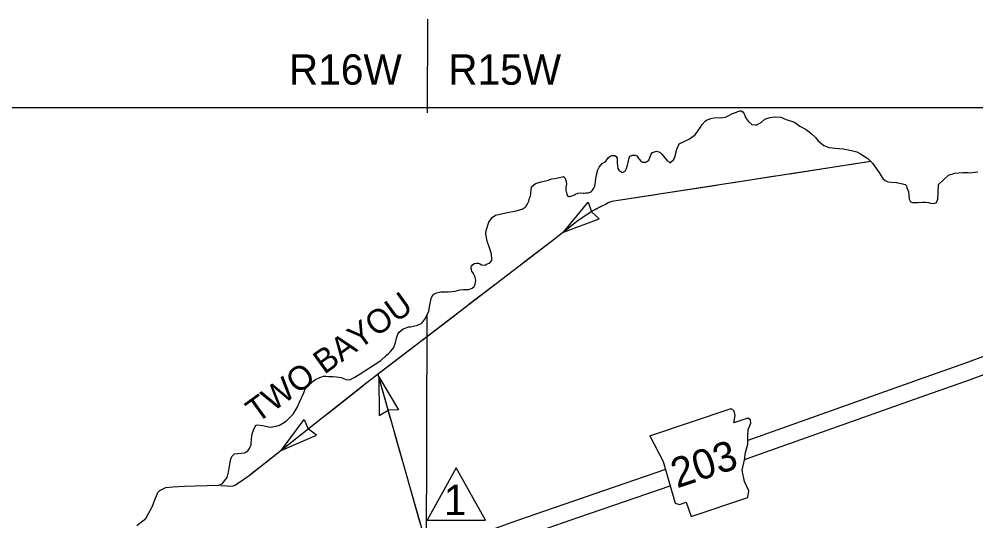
# Model space of a CAD drawing. Extents: x 1373094 to 1376427, y 1168361 to 1170494.
# Drawn here: x 1374665 to 1375232, y 1169290 to 1169586 of the extents above; entities that cross this region are included whole.
import ezdxf

# ---------------------------------------------------------------- set-up
doc = ezdxf.new("R2010")
doc.units = 0
for name, color, linetype in [('Default', 7, 'Continuous'), ('R_Axis', 7, 'Continuous'), ('R_Draft', 7, 'Continuous'), ('R_No Plot', 7, 'Continuous'), ('R_Water Annot', 7, 'Continuous')]:
    doc.layers.add(name, color=color, linetype=linetype)

msp = doc.modelspace()

# ---------------------------------------------------------------- linework, layer by layer
at = {"layer": 'R_Axis'}
for p, q in [((1374987.52, 1169460.32), (1375002.18, 1169478.15)), ((1375002.18, 1169478.15), (1375004.11, 1169472.37)), ((1374987.52, 1169460.32), (1375008.72, 1169468.27)), ((1375008.72, 1169468.27), (1375004.16, 1169472.3)), ((1374878.22, 1169374.82), (1374878.56, 1169351.94)), ((1374878.22, 1169374.82), (1374889.95, 1169355.17)), ((1374878.56, 1169351.94), (1374883.79, 1169355.06)), ((1374889.95, 1169355.17), (1374883.86, 1169355.08)), ((1375088.58, 1169354.46), (1375086.85, 1169355.94)), ((1374820.44, 1169331.13), (1374834.12, 1169349.47)), ((1374834.12, 1169349.47), (1374836.53, 1169343.88)), ((1375088.5, 1169347.6), (1375089.12, 1169351.97)), ((1375096.79, 1169350.37), (1375088.5, 1169347.6)), ((1375089.12, 1169351.97), (1375088.58, 1169354.46)), ((1375098.31, 1169349.39), (1375096.79, 1169350.37)), ((1375098.4, 1169347.34), (1375098.31, 1169349.39)), ((1374841.46, 1169340.17), (1374836.58, 1169343.81)), ((1375096.8, 1169339.67), (1375096.98, 1169343.6)), ((1375096.98, 1169343.6), (1375098.4, 1169347.34)), ((1374820.44, 1169331.13), (1374841.46, 1169340.17)), ((1375038.76, 1169339.85), (1375046.54, 1169324.62)), ((1375096.63, 1169334.86), (1375096.8, 1169339.67)), ((1375095.3, 1169329.95), (1375096.63, 1169334.86)), ((1375094.68, 1169325.58), (1375095.3, 1169329.95)), ((1375046.54, 1169324.62), (1375053.62, 1169299.93)), ((1375093.45, 1169319.52), (1375094.68, 1169325.58)), ((1375094.79, 1169312.83), (1375093.45, 1169319.52)), ((1375097.21, 1169307.39), (1375094.79, 1169312.83)), ((1375096.77, 1169303.38), (1375097.21, 1169307.39)), ((1375053.62, 1169299.93), (1375056.2, 1169299.31)), ((1375056.2, 1169299.31), (1375060.21, 1169300.65)), ((1375060.21, 1169300.65), (1375063.08, 1169292.1)), ((1375063.08, 1169292.1), (1375096.77, 1169303.38))]:
    msp.add_line(p, q, dxfattribs=at)
for points in [[(1374999.19, 1169483.51), (1374999.86, 1169483.38), (1375000.79, 1169483.52), (1375002.25, 1169483.53), (1375003.98, 1169484.21), (1375004.9, 1169485.41), (1375005.56, 1169486.35), (1375006.21, 1169487.56), (1375006.46, 1169489.96), (1375006.71, 1169492.23), (1375007.23, 1169494.24), (1375008.01, 1169497.18), (1375008.8, 1169498.79), (1375010.51, 1169500.93), (1375011.83, 1169501.74), (1375012.76, 1169502.41), (1375013.29, 1169503.22), (1375014.21, 1169504.43), (1375015.13, 1169505.37), (1375016.19, 1169505.77), (1375016.99, 1169505.78), (1375018.06, 1169505.65), (1375018.86, 1169505.12), (1375019.4, 1169504.19), (1375019.4, 1169503.65), (1375019.41, 1169501.39), (1375019.56, 1169499.65), (1375019.84, 1169497.92), (1375020.37, 1169497.12), (1375020.91, 1169496.59), (1375021.71, 1169496.06), (1375021.98, 1169495.93), (1375022.91, 1169495.93), (1375024.1, 1169496.34), (1375024.89, 1169497.95), (1375025.41, 1169499.95), (1375025.79, 1169501.56), (1375026.18, 1169503.29), (1375026.44, 1169504.36), (1375027.1, 1169505.3), (1375028.16, 1169505.98), (1375030.02, 1169505.99), (1375031.09, 1169505.46), (1375031.76, 1169504.39), (1375032.43, 1169503.6), (1375033.5, 1169502.13), (1375034.43, 1169501.74), (1375036.3, 1169501.75), (1375038.02, 1169502.96), (1375038.8, 1169504.57), (1375039.45, 1169506.57), (1375040.38, 1169507.51), (1375041.44, 1169507.92), (1375042.63, 1169508.2), (1375044.1, 1169507.94), (1375044.76, 1169507.54), (1375045.57, 1169506.61), (1375046.77, 1169505.28), (1375048.65, 1169503.16), (1375048.92, 1169502.62), (1375050.25, 1169501.7), (1375050.92, 1169501.43), (1375051.58, 1169502.24), (1375052.64, 1169503.18), (1375053.3, 1169504.12), (1375054.46, 1169508.4), (1375054.72, 1169509.47), (1375056.16, 1169512.55), (1375058.95, 1169513.9), (1375062.13, 1169515.52), (1375065.04, 1169517.54), (1375065.57, 1169517.94), (1375067.28, 1169520.49), (1375068.73, 1169522.37), (1375069.65, 1169523.97), (1375071.36, 1169525.99), (1375072.29, 1169526.66), (1375073.22, 1169527.06), (1375074.81, 1169527.61), (1375076.67, 1169528.02), (1375081.85, 1169528.18), (1375083.44, 1169528.46), (1375084.64, 1169529), (1375087.68, 1169530.49), (1375089.94, 1169531.43), (1375090.73, 1169531.71), (1375091.93, 1169532.11), (1375092.86, 1169532.12), (1375093.79, 1169531.46), (1375094.46, 1169530.39), (1375095.41, 1169528.13), (1375097.02, 1169525.87), (1375099.16, 1169524.01), (1375101.16, 1169523.75), (1375101.95, 1169523.89), (1375104.87, 1169525.51), (1375106.59, 1169526.99), (1375107.78, 1169527.67), (1375109.9, 1169528.21), (1375112.69, 1169528.63), (1375112.96, 1169528.63)], [(1374999.19, 1169483.51), (1374999.86, 1169483.38), (1375000.79, 1169483.52), (1375002.25, 1169483.53), (1375003.98, 1169484.21), (1375004.9, 1169485.41), (1375005.56, 1169486.35), (1375006.21, 1169487.56), (1375006.46, 1169489.96), (1375006.71, 1169492.23), (1375007.23, 1169494.24), (1375008.01, 1169497.18), (1375008.8, 1169498.79), (1375010.51, 1169500.93), (1375011.83, 1169501.74), (1375012.76, 1169502.41), (1375013.29, 1169503.22), (1375014.21, 1169504.43), (1375015.13, 1169505.37), (1375016.19, 1169505.77), (1375016.99, 1169505.78), (1375018.06, 1169505.65), (1375018.86, 1169505.12), (1375019.4, 1169504.19), (1375019.4, 1169503.65), (1375019.41, 1169501.39), (1375019.56, 1169499.65), (1375019.84, 1169497.92), (1375020.37, 1169497.12), (1375020.91, 1169496.59), (1375021.71, 1169496.06), (1375021.98, 1169495.93), (1375022.91, 1169495.93), (1375024.1, 1169496.34), (1375024.89, 1169497.95), (1375025.41, 1169499.95), (1375025.79, 1169501.56), (1375026.18, 1169503.29), (1375026.44, 1169504.36), (1375027.1, 1169505.3), (1375028.16, 1169505.98), (1375030.02, 1169505.99), (1375031.09, 1169505.46), (1375031.76, 1169504.39), (1375032.43, 1169503.6), (1375033.5, 1169502.13), (1375034.43, 1169501.74), (1375036.3, 1169501.75), (1375038.02, 1169502.96), (1375038.8, 1169504.57), (1375039.45, 1169506.57), (1375040.38, 1169507.51), (1375041.44, 1169507.92), (1375042.63, 1169508.2), (1375044.1, 1169507.94), (1375044.76, 1169507.54), (1375045.57, 1169506.61), (1375046.77, 1169505.28), (1375048.65, 1169503.16), (1375048.92, 1169502.62), (1375050.25, 1169501.7), (1375050.92, 1169501.43), (1375051.58, 1169502.24), (1375052.64, 1169503.18), (1375053.3, 1169504.12), (1375054.46, 1169508.4), (1375054.72, 1169509.47), (1375056.16, 1169512.55), (1375058.95, 1169513.9), (1375062.13, 1169515.52), (1375065.04, 1169517.54), (1375065.57, 1169517.94), (1375067.28, 1169520.49), (1375068.73, 1169522.37), (1375069.65, 1169523.97), (1375071.36, 1169525.99), (1375072.29, 1169526.66), (1375073.22, 1169527.06), (1375074.81, 1169527.61), (1375076.67, 1169528.02), (1375081.85, 1169528.18), (1375083.44, 1169528.46), (1375084.64, 1169529), (1375087.68, 1169530.49), (1375089.94, 1169531.43), (1375090.73, 1169531.71), (1375091.93, 1169532.11), (1375092.86, 1169532.12), (1375093.79, 1169531.46), (1375094.46, 1169530.39), (1375095.41, 1169528.13), (1375097.02, 1169525.87), (1375099.16, 1169524.01), (1375101.16, 1169523.75), (1375101.95, 1169523.89), (1375104.87, 1169525.51), (1375106.59, 1169526.99), (1375107.78, 1169527.67), (1375109.9, 1169528.21), (1375112.69, 1169528.63), (1375112.96, 1169528.63)], [(1375112.96, 1169528.63), (1375116.15, 1169528.38), (1375119.48, 1169527.07), (1375124.41, 1169525.36), (1375127.48, 1169523.11), (1375131.22, 1169520.99), (1375134.03, 1169519.01), (1375136.7, 1169516.35), (1375138.44, 1169514.36), (1375141.79, 1169511.71), (1375142.72, 1169511.31), (1375144.85, 1169510.52), (1375148.31, 1169510.14), (1375153.1, 1169509.64), (1375158.16, 1169508.6), (1375161.22, 1169507.81), (1375163.49, 1169506.76), (1375167.76, 1169503.85), (1375170.44, 1169501.19), (1375172.86, 1169497.74), (1375174.6, 1169495.21), (1375176.62, 1169492.02), (1375177.95, 1169490.96), (1375179.55, 1169490.16), (1375181.82, 1169489.91), (1375184.88, 1169489.66), (1375185.28, 1169489.53), (1375187.4, 1169489.14), (1375189.8, 1169488.49), (1375190.6, 1169487.83), (1375190.88, 1169486.63), (1375191.82, 1169484.36), (1375192.25, 1169479.82), (1375192.52, 1169479.02), (1375193.06, 1169478.36), (1375193.59, 1169478.1), (1375194.26, 1169477.97), (1375195.32, 1169477.97), (1375197.58, 1169477.99), (1375200.11, 1169478), (1375201.97, 1169478.14), (1375203.7, 1169477.89), (1375204.77, 1169477.49), (1375206.5, 1169477.37), (1375207.96, 1169477.65), (1375208.35, 1169477.91), (1375209.14, 1169479.92), (1375209.38, 1169483.66), (1375209.61, 1169488.6), (1375215.42, 1169494.11), (1375219.27, 1169495.33), (1375224.05, 1169495.63), (1375226.98, 1169495.65), (1375228.18, 1169495.52), (1375231.36, 1169495.8), (1375232.82, 1169496.08)], [(1375112.96, 1169528.63), (1375116.15, 1169528.38), (1375119.48, 1169527.07), (1375124.41, 1169525.36), (1375127.48, 1169523.11), (1375131.22, 1169520.99), (1375134.03, 1169519.01), (1375136.7, 1169516.35), (1375138.44, 1169514.36), (1375141.79, 1169511.71), (1375142.72, 1169511.31), (1375144.85, 1169510.52), (1375148.31, 1169510.14), (1375153.1, 1169509.64), (1375158.16, 1169508.6), (1375161.22, 1169507.81), (1375163.49, 1169506.76), (1375167.76, 1169503.85), (1375170.44, 1169501.19), (1375172.86, 1169497.74), (1375174.6, 1169495.21), (1375176.62, 1169492.02), (1375177.95, 1169490.96), (1375179.55, 1169490.16), (1375181.82, 1169489.91), (1375184.88, 1169489.66), (1375185.28, 1169489.53), (1375187.4, 1169489.14), (1375189.8, 1169488.49), (1375190.6, 1169487.83), (1375190.88, 1169486.63), (1375191.82, 1169484.36), (1375192.25, 1169479.82), (1375192.52, 1169479.02), (1375193.06, 1169478.36), (1375193.59, 1169478.1), (1375194.26, 1169477.97), (1375195.32, 1169477.97), (1375197.58, 1169477.99), (1375200.11, 1169478), (1375201.97, 1169478.14), (1375203.7, 1169477.89), (1375204.77, 1169477.49), (1375206.5, 1169477.37), (1375207.96, 1169477.65), (1375208.35, 1169477.91), (1375209.14, 1169479.92), (1375209.38, 1169483.66), (1375209.61, 1169488.6), (1375215.42, 1169494.11), (1375219.27, 1169495.33), (1375224.05, 1169495.63), (1375226.98, 1169495.65), (1375228.18, 1169495.52), (1375231.36, 1169495.8), (1375232.82, 1169496.08)], [(1375169.51, 1169502.12), (1375016.28, 1169478.47), (1375014.49, 1169477.84), (1375012.38, 1169476.74), (1375009.81, 1169475.56), (1375005.06, 1169472.95), (1374996.37, 1169467.2), (1374980.41, 1169454.79), (1374870.43, 1169370.58), (1374801.53, 1169316.2), (1374795.88, 1169312.24), (1374793.12, 1169310.47), (1374791.85, 1169310.1), (1374790.05, 1169309.95), (1374788.37, 1169310.03), (1374784.5, 1169310.25)], [(1375169.51, 1169502.12), (1375156.46, 1169500.1)], [(1375147.77, 1169498.76), (1375121.67, 1169494.73)], [(1374866.58, 1169376.07), (1374879.41, 1169384.42), (1374882.72, 1169387.38), (1374884.3, 1169388.85), (1374885.23, 1169389.79), (1374886.68, 1169391.4), (1374887.21, 1169392.07), (1374888.25, 1169395.15), (1374888.76, 1169397.69), (1374889.55, 1169400.1), (1374890.34, 1169401.17), (1374892.72, 1169403.19), (1374896.03, 1169404.41), (1374897.09, 1169404.42), (1374901.21, 1169405.37), (1374903.73, 1169406.59), (1374905.57, 1169408.87), (1374907.8, 1169413.42), (1374908.32, 1169416.23), (1374909.35, 1169421.04), (1374909.74, 1169422.11), (1374910.92, 1169423.59), (1374912.51, 1169424.4), (1374915.04, 1169425.08), (1374916.37, 1169425.09), (1374917.69, 1169425.1), (1374919.42, 1169425.11), (1374921.42, 1169425.25), (1374923.54, 1169425.53), (1374926.33, 1169426.21), (1374928.32, 1169426.49), (1374931.38, 1169426.38), (1374933.5, 1169427.19), (1374934.82, 1169428.27), (1374935.35, 1169429.47), (1374935.73, 1169432.01), (1374935.18, 1169434.41), (1374934.24, 1169435.87), (1374933.3, 1169437.34), (1374933.16, 1169438.27), (1374932.89, 1169438.93), (1374933.02, 1169439.34), (1374932.88, 1169439.87), (1374933.15, 1169440.27), (1374933.54, 1169440.81), (1374934.73, 1169441.88), (1374936.06, 1169442.02), (1374937.39, 1169442.03), (1374938.06, 1169441.64), (1374939.12, 1169440.97), (1374941.25, 1169440.85), (1374942.44, 1169441.53), (1374943.77, 1169442.07), (1374945.09, 1169443.54), (1374945.22, 1169444.48), (1374945.06, 1169447.42), (1374943.84, 1169451.01), (1374942.35, 1169455.01), (1374941.66, 1169459.15), (1374941.78, 1169461.42), (1374943.47, 1169466.23), (1374945.32, 1169469.05), (1374947.3, 1169470.39), (1374953.54, 1169471.76), (1374959.65, 1169473), (1374963.1, 1169473.96), (1374964.82, 1169475.17), (1374965.48, 1169475.71), (1374966.14, 1169476.78), (1374967.05, 1169478.65), (1374967.57, 1169480.52), (1374968.1, 1169481.73), (1374968.59, 1169487.21), (1374971.11, 1169489.09), (1374974.42, 1169490.04), (1374977.87, 1169490.86), (1374980.79, 1169491.82), (1374982.39, 1169492.09), (1374985.17, 1169492.64), (1374987.56, 1169493.19), (1374987.7, 1169493.19), (1374988.36, 1169492.53), (1374988.77, 1169491.59), (1374989.18, 1169490.26), (1374989.32, 1169488.66), (1374989.07, 1169486.79), (1374989.08, 1169484.92), (1374989.22, 1169484.25), (1374989.35, 1169483.72), (1374989.49, 1169483.05), (1374989.63, 1169482.39), (1374990.17, 1169481.72), (1374990.7, 1169481.46), (1374991.36, 1169481.46), (1374992.03, 1169481.6), (1374993.22, 1169482.01), (1374994.15, 1169482.41), (1374994.68, 1169482.82), (1374996.14, 1169483.36), (1374997.86, 1169483.64), (1374999.19, 1169483.51)], [(1374866.58, 1169376.07), (1374879.41, 1169384.42), (1374882.72, 1169387.38), (1374884.3, 1169388.85), (1374885.23, 1169389.79), (1374886.68, 1169391.4), (1374887.21, 1169392.07), (1374888.25, 1169395.15), (1374888.76, 1169397.69), (1374889.55, 1169400.1), (1374890.34, 1169401.17), (1374892.72, 1169403.19), (1374896.03, 1169404.41), (1374897.09, 1169404.42), (1374901.21, 1169405.37), (1374903.73, 1169406.59), (1374905.57, 1169408.87), (1374907.8, 1169413.42), (1374908.32, 1169416.23), (1374909.35, 1169421.04), (1374909.74, 1169422.11), (1374910.92, 1169423.59), (1374912.51, 1169424.4), (1374915.04, 1169425.08), (1374916.37, 1169425.09), (1374917.69, 1169425.1), (1374919.42, 1169425.11), (1374921.42, 1169425.25), (1374923.54, 1169425.53), (1374926.33, 1169426.21), (1374928.32, 1169426.49), (1374931.38, 1169426.38), (1374933.5, 1169427.19), (1374934.82, 1169428.27), (1374935.35, 1169429.47), (1374935.73, 1169432.01), (1374935.18, 1169434.41), (1374934.24, 1169435.87), (1374933.3, 1169437.34), (1374933.16, 1169438.27), (1374932.89, 1169438.93), (1374933.02, 1169439.34), (1374932.88, 1169439.87), (1374933.15, 1169440.27), (1374933.54, 1169440.81), (1374934.73, 1169441.88), (1374936.06, 1169442.02), (1374937.39, 1169442.03), (1374938.06, 1169441.64), (1374939.12, 1169440.97), (1374941.25, 1169440.85), (1374942.44, 1169441.53), (1374943.77, 1169442.07), (1374945.09, 1169443.54), (1374945.22, 1169444.48), (1374945.06, 1169447.42), (1374943.84, 1169451.01), (1374942.35, 1169455.01), (1374941.66, 1169459.15), (1374941.78, 1169461.42), (1374943.47, 1169466.23), (1374945.32, 1169469.05), (1374947.3, 1169470.39), (1374953.54, 1169471.76), (1374959.65, 1169473), (1374963.1, 1169473.96), (1374964.82, 1169475.17), (1374965.48, 1169475.71), (1374966.14, 1169476.78), (1374967.05, 1169478.65), (1374967.57, 1169480.52), (1374968.1, 1169481.73), (1374968.59, 1169487.21), (1374971.11, 1169489.09), (1374974.42, 1169490.04), (1374977.87, 1169490.86), (1374980.79, 1169491.82), (1374982.39, 1169492.09), (1374985.17, 1169492.64), (1374987.56, 1169493.19), (1374987.7, 1169493.19), (1374988.36, 1169492.53), (1374988.77, 1169491.59), (1374989.18, 1169490.26), (1374989.32, 1169488.66), (1374989.07, 1169486.79), (1374989.08, 1169484.92), (1374989.22, 1169484.25), (1374989.35, 1169483.72), (1374989.49, 1169483.05), (1374989.63, 1169482.39), (1374990.17, 1169481.72), (1374990.7, 1169481.46), (1374991.36, 1169481.46), (1374992.03, 1169481.6), (1374993.22, 1169482.01), (1374994.15, 1169482.41), (1374994.68, 1169482.82), (1374996.14, 1169483.36), (1374997.86, 1169483.64), (1374999.19, 1169483.51)], [(1375112.98, 1169493.39), (1375086.89, 1169489.36)], [(1375078.19, 1169488.02), (1375052.1, 1169484)], [(1375043.4, 1169482.65), (1375017.31, 1169478.63)], [(1375009.24, 1169475.25), (1375005.06, 1169472.95), (1374996.37, 1169467.2), (1374987.52, 1169460.32)], [(1374980.57, 1169454.92), (1374980.41, 1169454.79), (1374970.09, 1169446.89)], [(1374970.09, 1169446.89), (1374959.61, 1169438.87)], [(1374952.62, 1169433.52), (1374931.66, 1169417.47)], [(1375333.54, 1169420.56), (1375256.62, 1169394.37), (1375225.05, 1169382.65), (1375195.38, 1169372.11), (1375096.71, 1169337.09)], [(1374924.67, 1169412.12), (1374903.71, 1169396.07)], [(1374906.66, 1169411.1), (1374906.32, 1169269.99)], [(1375094.71, 1169325.77), (1375198.72, 1169362.68), (1375228.46, 1169373.25), (1375259.98, 1169384.95), (1375323.36, 1169406.53)], [(1374896.72, 1169390.72), (1374875.76, 1169374.67)], [(1374830.01, 1169356.63), (1374831.32, 1169359.71), (1374833.68, 1169364.93), (1374834.46, 1169366.94), (1374834.46, 1169367.34), (1374836.05, 1169369.08), (1374839.35, 1169372.17), (1374840.8, 1169373.25), (1374843.32, 1169374.46), (1374845.58, 1169375.14), (1374847.17, 1169375.15), (1374848.77, 1169375.03), (1374851.03, 1169374.91), (1374853.16, 1169374.79), (1374855.95, 1169374.27), (1374859.02, 1169373.22), (1374861.15, 1169372.97), (1374863.66, 1169374.32), (1374866.58, 1169376.07)], [(1374830.01, 1169356.63), (1374831.32, 1169359.71), (1374833.68, 1169364.93), (1374834.46, 1169366.94), (1374834.46, 1169367.34), (1374836.05, 1169369.08), (1374839.35, 1169372.17), (1374840.8, 1169373.25), (1374843.32, 1169374.46), (1374845.58, 1169375.14), (1374847.17, 1169375.15), (1374848.77, 1169375.03), (1374851.03, 1169374.91), (1374853.16, 1169374.79), (1374855.95, 1169374.27), (1374859.02, 1169373.22), (1374861.15, 1169372.97), (1374863.66, 1169374.32), (1374866.58, 1169376.07)], [(1374990.01, 1168990.5), (1374989.46, 1168991.36), (1374987.1, 1168997), (1374982.47, 1169011.56), (1374979.67, 1169019.8), (1374976.73, 1169028.3), (1374975.26, 1169036.23), (1374970.65, 1169053.39), (1374953.09, 1169115.44), (1374934.6, 1169177.81), (1374897.2, 1169307.95), (1374877.82, 1169376.24)], [(1374885.43, 1169349.42), (1374878.22, 1169374.82)], [(1374868.79, 1169369.3), (1374848.07, 1169352.94)], [(1374735.16, 1169286.79), (1374740.32, 1169290.96), (1374744.26, 1169298.19), (1374745.3, 1169301), (1374747.4, 1169306.35), (1374748.58, 1169307.56), (1374752.29, 1169309.32), (1374756.28, 1169309.74), (1374763.19, 1169310.05), (1374769.57, 1169310.22), (1374776.75, 1169310.53), (1374783.39, 1169310.7), (1374785.52, 1169311.38), (1374788.55, 1169315.14), (1374789.33, 1169318.34), (1374790.09, 1169323.15), (1374790.74, 1169326.1), (1374791.39, 1169327.7), (1374792.84, 1169329.18), (1374798.82, 1169329.88), (1374799.62, 1169330.15), (1374800.67, 1169330.96), (1374801.73, 1169332.3), (1374802.78, 1169334.71), (1374803.02, 1169338.18), (1374803.26, 1169340.99), (1374804.05, 1169343.26), (1374804.7, 1169344.6), (1374805.62, 1169346.07), (1374806.42, 1169346.35), (1374809.48, 1169345.96), (1374813.21, 1169345.18), (1374814.27, 1169344.92), (1374817.46, 1169345.48), (1374819.58, 1169346.16), (1374823.42, 1169348.45), (1374825.93, 1169351), (1374827.51, 1169352.74), (1374830.01, 1169356.63)], [(1374783.14, 1169310.69), (1374783.39, 1169310.7), (1374785.52, 1169311.38), (1374788.55, 1169315.14), (1374789.33, 1169318.34), (1374790.09, 1169323.15), (1374790.74, 1169326.1), (1374791.39, 1169327.7), (1374792.84, 1169329.18), (1374798.82, 1169329.88), (1374799.62, 1169330.15), (1374800.67, 1169330.96), (1374801.73, 1169332.3), (1374802.78, 1169334.71), (1374803.02, 1169338.18), (1374803.26, 1169340.99), (1374804.05, 1169343.26), (1374804.7, 1169344.6), (1374805.62, 1169346.07), (1374806.42, 1169346.35), (1374809.48, 1169345.96), (1374813.21, 1169345.18), (1374814.27, 1169344.92), (1374817.46, 1169345.48), (1374819.58, 1169346.16), (1374823.42, 1169348.45), (1374825.93, 1169351), (1374827.51, 1169352.74), (1374830.01, 1169356.63)], [(1375038.76, 1169339.85), (1375086.85, 1169355.94)], [(1374841.17, 1169347.49), (1374820.44, 1169331.13)], [(1374895.04, 1169315.56), (1374887.83, 1169340.95)], [(1374813.54, 1169325.68), (1374803.17, 1169317.5)], [(1374803.17, 1169317.5), (1374801.53, 1169316.2), (1374795.88, 1169312.24), (1374793.12, 1169310.47), (1374792.23, 1169310.21)], [(1375047.9, 1169319.87), (1374993.51, 1169301.24), (1374970.66, 1169293.33), (1374957.07, 1169288.57), (1374932.54, 1169279.71)], [(1374935.94, 1169270.3), (1374960.42, 1169279.14), (1374973.95, 1169283.89), (1374996.76, 1169291.79), (1375050.66, 1169310.25)], [(1374903.02, 1169287.69), (1374897.44, 1169307.09)]]:
    msp.add_lwpolyline(points, dxfattribs=at)
at = {"layer": 'R_Draft'}
msp.add_lwpolyline([(1374924.14, 1169320.94), (1374906.83, 1169289.93), (1374941.45, 1169289.93)], close=True, dxfattribs=at)
at = {"layer": 'R_No Plot'}
msp.add_lwpolyline([(1373989.53, 1169534.16), (1375496.95, 1169534.16), (1375496.95, 1168608.52), (1373989.53, 1168608.52)], close=True, dxfattribs=at)
at = {"layer": 'R_Water Annot'}
msp.add_line((1374907.09, 1169586.38), (1374906.95, 1169530.96), dxfattribs=at)

# ---------------------------------------------------------------- texts
at = {"layer": 'Default'}
for s, p in [('R16W', (1374825.04, 1169547.58)), ('R15W', (1374919.35, 1169547.58))]:
    msp.add_text(s, height=18, dxfattribs=at).set_placement(p)
at = {"layer": 'R_Axis'}
msp.add_text('203', height=17.6, rotation=18.5187, dxfattribs=at).set_placement((1375054.8, 1169308.69))
at = {"layer": 'R_Draft'}
msp.add_text('1', height=18, dxfattribs=at).set_placement((1374916.77, 1169292.93))
at = {"layer": 'R_Water Annot'}
msp.add_text('TWO BAYOU', height=14.08, rotation=35.8837, dxfattribs=at).set_placement((1374806.23, 1169347.02))

doc.saveas('drawing.dxf')
